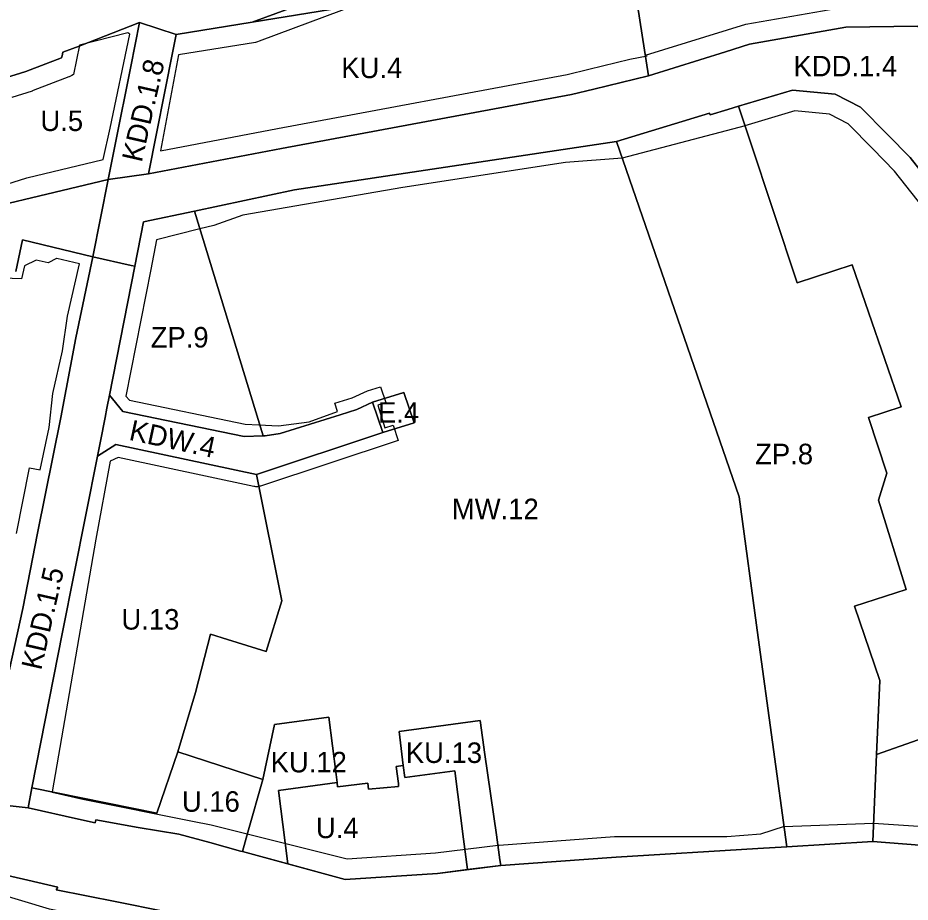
# Model space of a CAD drawing. Extents: x 7421913 to 7423341, y 5550123 to 5551175.
# Drawn here: x 7422401.5 to 7422618.9, y 5550727.7 to 5550943.3 of the extents above; entities that cross this region are included whole.
import ezdxf

# ---------------------------------------------------------------- set-up
doc = ezdxf.new("R2010")
doc.units = 0
for name, color, linetype in [('linie_rozgraniczajace', 7, 'Continuous'), ('linie_zabudowy_nieprzekraczalne', 7, 'Continuous'), ('oznaczenia_przeznaczen', 7, 'Continuous')]:
    doc.layers.add(name, color=color, linetype=linetype)

msp = doc.modelspace()

# ---------------------------------------------------------------- linework, layer by layer
at = {"layer": 'linie_rozgraniczajace'}
for points in [[(7422660.2, 5550995.93), (7422736.14, 5550871.82), (7422746.45, 5550839.81), (7422775.86, 5550739.06), (7422774.83, 5550732.45), (7422771.39, 5550729.31), (7422738.92, 5550731.51), (7422701.03, 5550733.87), (7422675.81, 5550735.06), (7422667.52, 5550743.81), (7422665.8, 5550778.51), (7422665.93, 5550827.56), (7422664.73, 5550868.38), (7422658.65, 5550888.31), (7422649.82, 5550905.1), (7422641.09, 5550916.01), (7422620.84, 5550941.29), (7422603.26, 5550941.04), (7422579.8, 5550936.89), (7422573.93, 5550935.06), (7422555.21, 5550929.23), (7422550.98, 5550956.47)], [(7422487.44, 5550952.92), (7422458.59, 5550942.31), (7422440.1, 5550939.32), (7422431.14, 5550942.19), (7422416.39, 5550936.46), (7422412.46, 5550934.94), (7422412.25, 5550934.1), (7422412.12, 5550933.61), (7422403.43, 5550930.26), (7422398.51, 5550928.69), (7422370.22, 5550921.41), (7422364.38, 5550919.91), (7422337.59, 5550913.65), (7422294.17, 5550904.39), (7422254.92, 5550901.03), (7422233.03, 5550897.49), (7422228.24, 5550896.09), (7422225.63, 5550895.33), (7422220.81, 5550893.92)], [(7422485.73, 5550946.7), (7422458.59, 5550942.31), (7422487.44, 5550952.92)], [(7422631.31, 5550893.52), (7422618.9, 5550909.29), (7422613.41, 5550914.88), (7422606.86, 5550921.55), (7422600.68, 5550924.76), (7422590.3, 5550925.74), (7422577.14, 5550921.79), (7422574.5, 5550920.99), (7422570.17, 5550919.69), (7422570.05, 5550920.11), (7422547.37, 5550913.21), (7422468.9, 5550901.4), (7422444.57, 5550896.23), (7422432.1, 5550893.58), (7422429.98, 5550882.78), (7422429.13, 5550882.96), (7422419.77, 5550885.08), (7422423.53, 5550903.95), (7422433.32, 5550905.32), (7422465.71, 5550911.45), (7422536.44, 5550924.64), (7422541.83, 5550925.96), (7422551.82, 5550928.4), (7422555.21, 5550929.23), (7422573.93, 5550935.06), (7422579.8, 5550936.89), (7422603.26, 5550941.04), (7422620.84, 5550941.29)], [(7422626.65, 5550769.34), (7422610.77, 5550763.7), (7422611.58, 5550781.76), (7422605.35, 5550799.85), (7422617.99, 5550803.97), (7422611.2, 5550825.7), (7422613.21, 5550832.3), (7422608.76, 5550845.86), (7422616.76, 5550848.49), (7422604.8, 5550883.14), (7422591.36, 5550878.76), (7422579.87, 5550913.52), (7422577.14, 5550921.79), (7422590.3, 5550925.74), (7422600.68, 5550924.76), (7422606.86, 5550921.55), (7422613.41, 5550914.88), (7422618.9, 5550909.29), (7422631.31, 5550893.52)], [(7422393.88, 5550896.84), (7422404.82, 5550899.45), (7422423.53, 5550903.95), (7422419.77, 5550885.08), (7422402.63, 5550889.21), (7422401, 5550881.52)], [(7422401, 5550881.52), (7422402.63, 5550889.21), (7422419.77, 5550885.08), (7422415.62, 5550865.28), (7422411.97, 5550845.88), (7422406.26, 5550817.72), (7422402.67, 5550799.3), (7422398.8, 5550781.52)], [(7422436.89, 5550725.5), (7422425.59, 5550727.79), (7422410.79, 5550730.73), (7422411.25, 5550731.36), (7422403.89, 5550733.09), (7422400.05, 5550733.99), (7422393.38, 5550735.82), (7422389.77, 5550734.83), (7422370.59, 5550739.24), (7422354.55, 5550742.84), (7422340.93, 5550745.68), (7422336.5, 5550749.5), (7422316.61, 5550753.63), (7422266.97, 5550763.62), (7422250.63, 5550767.05), (7422241.68, 5550768.92), (7422235.34, 5550770.25), (7422213.4, 5550774.82)], [(7422393.67, 5550751.85), (7422404, 5550750.7), (7422416.24, 5550747.98), (7422420.34, 5550747.09), (7422420.49, 5550747.82), (7422430.83, 5550745.95), (7422440.72, 5550744.32), (7422448.24, 5550742.24), (7422455.75, 5550740.17), (7422456.2, 5550740.05), (7422481.24, 5550733.27), (7422503.72, 5550734.73), (7422519.15, 5550736.64), (7422547.29, 5550738.7), (7422581.81, 5550740.81), (7422588.85, 5550741.23), (7422609.82, 5550742.52), (7422650.24, 5550739.36)]]:
    msp.add_lwpolyline(points, dxfattribs=at)
for points in [[(7422433.32, 5550905.32), (7422439.27, 5550935.21), (7422440.1, 5550939.32), (7422458.59, 5550942.31), (7422485.73, 5550946.7), (7422530.12, 5550953.22), (7422532.68, 5550953.62), (7422550.98, 5550956.47), (7422555.21, 5550929.23), (7422551.82, 5550928.4), (7422541.83, 5550925.96), (7422536.44, 5550924.64), (7422465.71, 5550911.45)], [(7422404.82, 5550899.45), (7422393.88, 5550896.84), (7422394.59, 5550901.4), (7422397.89, 5550923.41), (7422398.27, 5550926.65), (7422398.51, 5550928.69), (7422403.43, 5550930.26), (7422412.12, 5550933.61), (7422412.25, 5550934.1), (7422412.46, 5550934.94), (7422416.39, 5550936.46), (7422431.14, 5550942.19), (7422429, 5550931.44), (7422425.22, 5550912.43), (7422423.53, 5550903.95)], [(7422440.1, 5550939.32), (7422439.27, 5550935.21), (7422433.32, 5550905.32), (7422423.53, 5550903.95), (7422425.22, 5550912.43), (7422429, 5550931.44), (7422431.14, 5550942.19)], [(7422610.77, 5550763.7), (7422609.82, 5550742.52), (7422588.85, 5550741.23), (7422581.91, 5550792.22), (7422577.24, 5550826.55), (7422547.37, 5550913.21), (7422570.05, 5550920.11), (7422570.17, 5550919.69), (7422574.5, 5550920.99), (7422577.14, 5550921.79), (7422579.87, 5550913.52), (7422591.36, 5550878.76), (7422604.8, 5550883.14), (7422616.76, 5550848.49), (7422608.76, 5550845.86), (7422613.21, 5550832.3), (7422611.2, 5550825.7), (7422617.99, 5550803.97), (7422605.35, 5550799.85), (7422611.58, 5550781.76)], [(7422515.31, 5550763.75), (7422514.13, 5550772.05), (7422494.37, 5550769.36), (7422495.42, 5550761.03), (7422493.69, 5550760.79), (7422494.21, 5550756.63), (7422494.28, 5550755.93), (7422486.97, 5550755.3), (7422486.74, 5550756.73), (7422479.41, 5550755.86), (7422479.28, 5550756.87), (7422479.03, 5550758.86), (7422477.31, 5550772.84), (7422464.06, 5550771.07), (7422461.22, 5550757.65), (7422440.47, 5550764.4), (7422444.75, 5550778.85), (7422448.46, 5550793.03), (7422452.59, 5550791.79), (7422461.98, 5550788.83), (7422465.83, 5550801.19), (7422459.65, 5550832.01), (7422490.44, 5550842.21), (7422498.07, 5550844.62), (7422495.56, 5550852.01), (7422487.94, 5550849.67), (7422484.1, 5550847.88), (7422480.07, 5550846.52), (7422465.43, 5550841.99), (7422461.72, 5550841.41), (7422461.23, 5550841.4), (7422444.57, 5550896.23), (7422468.9, 5550901.4), (7422547.37, 5550913.21), (7422577.24, 5550826.55), (7422581.91, 5550792.22), (7422588.85, 5550741.23), (7422581.81, 5550740.81), (7422547.29, 5550738.7), (7422519.15, 5550736.64), (7422518.95, 5550738.01), (7422518.09, 5550744.11)], [(7422461.23, 5550841.4), (7422456.61, 5550841.3), (7422427.05, 5550847.37), (7422423.8, 5550851.32), (7422429.98, 5550882.78), (7422432.1, 5550893.58), (7422444.57, 5550896.23)], [(7422429.98, 5550882.78), (7422423.8, 5550851.32), (7422423.18, 5550848.17), (7422422.74, 5550845.9), (7422421.6, 5550840.11), (7422420.88, 5550836.46), (7422412.36, 5550793.58), (7422404.93, 5550755.58), (7422404, 5550750.7), (7422393.67, 5550751.85), (7422391.33, 5550752.11), (7422392.9, 5550753.58), (7422394.98, 5550763.42), (7422398.8, 5550781.52), (7422402.67, 5550799.3), (7422406.26, 5550817.72), (7422411.97, 5550845.88), (7422415.62, 5550865.28), (7422419.77, 5550885.08), (7422429.13, 5550882.96)], [(7422461.23, 5550841.4), (7422461.72, 5550841.41), (7422465.43, 5550841.99), (7422480.07, 5550846.52), (7422484.1, 5550847.88), (7422487.94, 5550849.67), (7422490.44, 5550842.21), (7422459.65, 5550832.01), (7422425.35, 5550839.31), (7422420.88, 5550836.46), (7422421.6, 5550840.11), (7422422.74, 5550845.9), (7422423.18, 5550848.17), (7422423.8, 5550851.32), (7422427.05, 5550847.37), (7422456.61, 5550841.3)], [(7422490.44, 5550842.21), (7422487.94, 5550849.67), (7422495.56, 5550852.01), (7422498.07, 5550844.62)], [(7422459.65, 5550832.01), (7422465.83, 5550801.19), (7422461.98, 5550788.83), (7422452.59, 5550791.79), (7422448.46, 5550793.03), (7422444.75, 5550778.85), (7422440.47, 5550764.4), (7422435.39, 5550749.4), (7422404.93, 5550755.58), (7422412.36, 5550793.58), (7422420.88, 5550836.46), (7422425.35, 5550839.31)], [(7422650.24, 5550739.36), (7422609.82, 5550742.52), (7422610.77, 5550763.7), (7422626.65, 5550769.34), (7422633.46, 5550771.71), (7422639.81, 5550774.05), (7422643.86, 5550775.53), (7422646.53, 5550776.5), (7422655.25, 5550753.04)], [(7422466.64, 5550742.21), (7422467.29, 5550737.05), (7422456.2, 5550740.05), (7422457.54, 5550744.76), (7422461.22, 5550757.65), (7422464.06, 5550771.07), (7422477.31, 5550772.84), (7422479.03, 5550758.86), (7422479.28, 5550756.87), (7422464.99, 5550754.96)], [(7422515.31, 5550763.75), (7422518.09, 5550744.11), (7422518.95, 5550738.01), (7422519.15, 5550736.64), (7422511.07, 5550735.64), (7422510.08, 5550743.07), (7422507.96, 5550759.77), (7422495.8, 5550758.13), (7422495.42, 5550761.03), (7422494.37, 5550769.36), (7422514.13, 5550772.05)], [(7422461.22, 5550757.65), (7422457.54, 5550744.76), (7422456.2, 5550740.05), (7422455.75, 5550740.17), (7422448.24, 5550742.24), (7422440.72, 5550744.32), (7422430.83, 5550745.95), (7422420.49, 5550747.82), (7422420.34, 5550747.09), (7422416.24, 5550747.98), (7422404, 5550750.7), (7422404.93, 5550755.58), (7422435.39, 5550749.4), (7422440.47, 5550764.4)], [(7422511.07, 5550735.64), (7422503.72, 5550734.73), (7422481.24, 5550733.27), (7422467.29, 5550737.05), (7422466.64, 5550742.21), (7422464.99, 5550754.96), (7422479.28, 5550756.87), (7422479.41, 5550755.86), (7422486.74, 5550756.73), (7422486.97, 5550755.3), (7422494.28, 5550755.93), (7422494.21, 5550756.63), (7422493.69, 5550760.79), (7422495.42, 5550761.03), (7422495.8, 5550758.13), (7422507.96, 5550759.77), (7422510.08, 5550743.07)], [(7422454.96, 5550722.08), (7422451.28, 5550712.14), (7422483.54, 5550700.93), (7422481.91, 5550688.66), (7422474.43, 5550684.56), (7422444.95, 5550694.93), (7422433.33, 5550699.08), (7422427.58, 5550701.09), (7422417.05, 5550704.79), (7422403.17, 5550709.84), (7422389.47, 5550714.93), (7422388.85, 5550715.6), (7422391.17, 5550725.97), (7422392.79, 5550733.16), (7422393.38, 5550735.82), (7422400.05, 5550733.99), (7422403.89, 5550733.09), (7422411.25, 5550731.36), (7422410.79, 5550730.73), (7422425.59, 5550727.79), (7422436.89, 5550725.5), (7422442.35, 5550724.39)]]:
    msp.add_lwpolyline(points, close=True, dxfattribs=at)
at = {"layer": 'linie_zabudowy_nieprzekraczalne'}
for points in [[(7422484.53, 5550946.67), (7422460.32, 5550937.62), (7422459.88, 5550937.48), (7422459.39, 5550937.37), (7422440.66, 5550934.35), (7422436.25, 5550910.93)], [(7422554.43, 5550934.23), (7422578.93, 5550941.81), (7422603.19, 5550946.04), (7422622.55, 5550945.99), (7422653.72, 5550908.22), (7422663.08, 5550890.64), (7422669.65, 5550869.25), (7422670.8, 5550778.63), (7422672.43, 5550745.91), (7422678.04, 5550739.96)], [(7422372.01, 5550894.36), (7422403.66, 5550904.31), (7422422.29, 5550908.78), (7422423.95, 5550916.43), (7422428.77, 5550939.37), (7422428.3, 5550939.71)], [(7422428.3, 5550939.72), (7422416.48, 5550936.65), (7422415.01, 5550929.51), (7422414.62, 5550929.28), (7422414.33, 5550929.13), (7422414.03, 5550928.99), (7422413.92, 5550928.94), (7422405.23, 5550925.59), (7422405.04, 5550925.53), (7422404.95, 5550925.5), (7422400.03, 5550923.93)], [(7422436.25, 5550910.93), (7422464.78, 5550916.36), (7422464.79, 5550916.37), (7422535.39, 5550929.53), (7422540.64, 5550930.82), (7422540.64, 5550930.82), (7422550.63, 5550933.26), (7422554.86, 5550934.1)], [(7422590.8, 5550920.67), (7422578.65, 5550917.02)], [(7422588.18, 5550746.17), (7422610.02, 5550747.01), (7422646.67, 5550744.54), (7422649.92, 5550753.03), (7422648.89, 5550756.7), (7422644.55, 5550768.66), (7422646.02, 5550769.08), (7422641.76, 5550780.48), (7422643, 5550802.27), (7422642.84, 5550859.8), (7422633.44, 5550886.58), (7422628.85, 5550889.17), (7422628.81, 5550889.19), (7422628.53, 5550889.36), (7422628.27, 5550889.55), (7422628.01, 5550889.76), (7422627.77, 5550889.98), (7422627.55, 5550890.22), (7422627.38, 5550890.43), (7422615.14, 5550905.98), (7422609.84, 5550911.38), (7422603.85, 5550917.48), (7422599.24, 5550919.87), (7422590.8, 5550920.67)], [(7422578.71, 5550917.04), (7422548.77, 5550909.15), (7422534.94, 5550908.04), (7422495.32, 5550901.98), (7422456.35, 5550895.27), (7422449.26, 5550892.75), (7422445.87, 5550891.86)], [(7422445.87, 5550891.86), (7422435.28, 5550889.25), (7422433.9, 5550882.01), (7422427.84, 5550851.13), (7422428.69, 5550850.1), (7422456.88, 5550844.3), (7422460.22, 5550844.14)], [(7422410.9, 5550884.7), (7422408.85, 5550883.6), (7422405.97, 5550884.23), (7422403.14, 5550882.87), (7422402.4, 5550879.72), (7422393.12, 5550880.04)], [(7422401.14, 5550817.58), (7422404.34, 5550833.63), (7422406.96, 5550833.1), (7422409.11, 5550843.43), (7422410.01, 5550851.72), (7422412.37, 5550862.15), (7422413.62, 5550870.6), (7422416.51, 5550883.39), (7422411, 5550884.7)], [(7422460.22, 5550844.14), (7422465.02, 5550843.9), (7422472.48, 5550844.83), (7422479.38, 5550847.34), (7422478.72, 5550849.4), (7422482.98, 5550850.67), (7422486.67, 5550852.39), (7422489.83, 5550853.36), (7422491.14, 5550849.55), (7422489.21, 5550848.92), (7422490.93, 5550843.39), (7422492.98, 5550844.06), (7422494.19, 5550840.28), (7422460.59, 5550829.16), (7422460.43, 5550829.11), (7422460.24, 5550829.07), (7422460.04, 5550829.04), (7422459.85, 5550829.02), (7422459.65, 5550829.01), (7422459.45, 5550829.02), (7422459.26, 5550829.04), (7422459.06, 5550829.07), (7422459.03, 5550829.08), (7422425.93, 5550836.12), (7422424, 5550835.22), (7422420.46, 5550816.21), (7422409.84, 5550754.63), (7422409.82, 5550754.53), (7422417.31, 5550752.86), (7422444.04, 5550747.49), (7422448.61, 5550746.56), (7422481.74, 5550738.31), (7422503.25, 5550739.71), (7422518.54, 5550741.6), (7422518.78, 5550741.63), (7422546.92, 5550743.69), (7422546.96, 5550743.69), (7422546.98, 5550743.69), (7422574.24, 5550743.71), (7422582.53, 5550744.37), (7422588.28, 5550746.21)], [(7422397.31, 5550734.1), (7422393.4, 5550734.85), (7422389.39, 5550716.95), (7422402.44, 5550712.28), (7422408.31, 5550709.95), (7422417.64, 5550706.69), (7422427.89, 5550702.59), (7422456.51, 5550692.24), (7422459.96, 5550690), (7422467.33, 5550687.39), (7422480.75, 5550693.45), (7422482.8, 5550707.62), (7422483.27, 5550712.28), (7422460.61, 5550720.12), (7422459.4, 5550716.2), (7422441.37, 5550719.49), (7422441.35, 5550719.49), (7422435.9, 5550720.6), (7422424.61, 5550722.89), (7422409.18, 5550726), (7422396.47, 5550729.81), (7422397.4, 5550734.29)]]:
    msp.add_lwpolyline(points, dxfattribs=at)

# ---------------------------------------------------------------- texts
at = {"layer": 'oznaczenia_przeznaczen'}
for s, rotation, p in [('KDD.1.8', 77.1654, (7422431.66, 5550907.92)), ('KDW.4', 347.7828, (7422428.36, 5550840.49)), ('KDD.1.5', 77.1654, (7422407.16, 5550784.08))]:
    msp.add_text(s, height=5, rotation=rotation, dxfattribs=at).set_placement(p)
for s, p in [('KU.4', (7422480.31, 5550928.65)), ('KDD.1.4', (7422590.5, 5550929.08)), ('U.5', (7422406.99, 5550915.75)), ('ZP.9', (7422433.85, 5550862.96)), ('E.4', (7422489.24, 5550844.62)), ('ZP.8', (7422581.16, 5550834.49)), ('MW.12', (7422507.25, 5550821.1)), ('U.13', (7422426.73, 5550794.18)), ('KU.13', (7422496.03, 5550761.66)), ('KU.12', (7422463.08, 5550759.36)), ('U.16', (7422441.46, 5550749.76)), ('U.4', (7422474.12, 5550743.32))]:
    msp.add_text(s, height=5, dxfattribs=at).set_placement(p)

doc.saveas('drawing.dxf')
